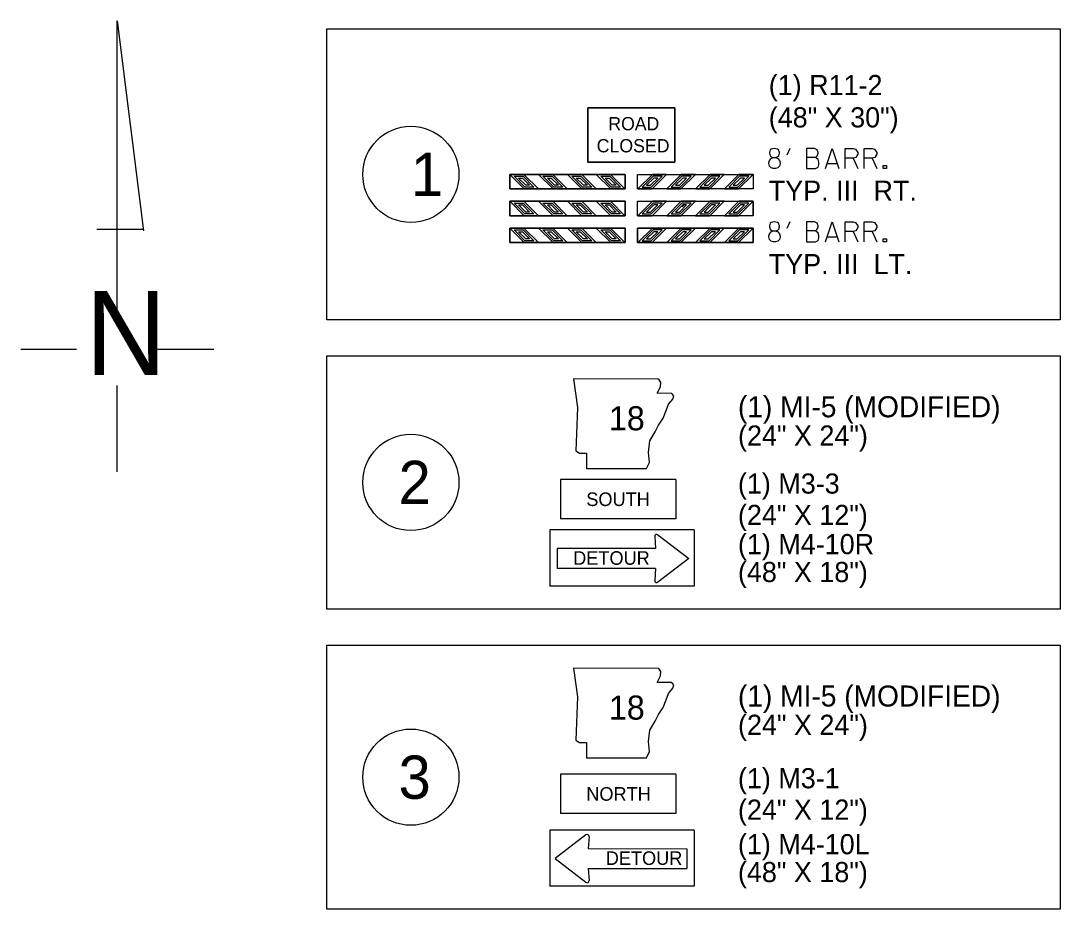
# Model space of a CAD drawing. Extents: x -31818 to 1228740, y -23925 to 152440.
# Drawn here: x -31817.88 to -31789.07, y -23847.72 to -23823.11 of the extents above; entities that cross this region are included whole.
import ezdxf

# ---------------------------------------------------------------- set-up
doc = ezdxf.new("R2010")
doc.units = 0
for name, color, linetype in [('21', 7, 'Continuous'), ('3', 7, 'Continuous'), ('59', 7, 'Continuous'), ('8', 7, 'Continuous'), ('Level 3', 7, 'Continuous'), ('Level 8', 7, 'Continuous'), ('shading', 7, 'Continuous')]:
    doc.layers.add(name, color=color, linetype=linetype)

msp = doc.modelspace()

# ---------------------------------------------------------------- linework, layer by layer
at = {"layer": '21'}
for points in [[(-31802.563, -23833.03), (-31802.445, -23833.822), (-31802.499, -23835.023), (-31802.394, -23835.089), (-31802.196, -23835.089), (-31802.196, -23835.511), (-31800.534, -23835.513), (-31800.454, -23835.341), (-31800.481, -23835.064), (-31800.441, -23834.747), (-31800.295, -23834.497), (-31800.203, -23834.312), (-31800.07, -23834.115), (-31799.991, -23833.904), (-31799.925, -23833.732), (-31799.806, -23833.587), (-31799.779, -23833.495), (-31799.832, -23833.429), (-31800.242, -23833.428), (-31800.149, -23833.244), (-31800.135, -23833.125), (-31800.19, -23833.034)], [(-31802.563, -23841.045), (-31802.445, -23841.837), (-31802.499, -23843.038), (-31802.394, -23843.104), (-31802.196, -23843.104), (-31802.196, -23843.527), (-31800.534, -23843.528), (-31800.454, -23843.357), (-31800.481, -23843.079), (-31800.441, -23842.763), (-31800.295, -23842.512), (-31800.203, -23842.328), (-31800.07, -23842.13), (-31799.991, -23841.919), (-31799.925, -23841.747), (-31799.806, -23841.602), (-31799.779, -23841.51), (-31799.832, -23841.444), (-31800.242, -23841.444), (-31800.149, -23841.259), (-31800.135, -23841.14), (-31800.19, -23841.049)]]:
    msp.add_lwpolyline(points, close=True, dxfattribs=at)
at = {"layer": '3'}
for centre, start, end in [((-31800.254, -23837.39), 52.3853, 184.5739), ((-31800.254, -23838.618), 175.4261, 307.6112), ((-31802.181, -23845.706), 355.4261, 127.6147), ((-31802.181, -23846.934), 232.3888, 4.5739)]:
    msp.add_arc(centre, 0.055, start, end, dxfattribs=at)
at = {"layer": '59'}
for p, q in [((-31799.719, -23835.82), (-31802.92, -23835.82)), ((-31802.92, -23835.82), (-31802.92, -23836.906)), ((-31799.719, -23835.82), (-31799.719, -23836.906)), ((-31799.719, -23836.906), (-31802.92, -23836.906)), ((-31799.211, -23837.213), (-31803.217, -23837.213)), ((-31803.217, -23837.213), (-31803.217, -23838.771)), ((-31800.309, -23837.395), (-31800.282, -23837.729)), ((-31800.22, -23837.347), (-31799.366, -23838.004)), ((-31799.211, -23837.213), (-31799.211, -23838.77)), ((-31800.282, -23837.729), (-31803.015, -23837.729)), ((-31803.015, -23837.729), (-31803.015, -23838.28)), ((-31799.366, -23838.004), (-31800.22, -23838.662)), ((-31800.282, -23838.279), (-31803.015, -23838.28)), ((-31800.282, -23838.279), (-31800.308, -23838.614)), ((-31799.211, -23838.77), (-31803.217, -23838.771)), ((-31799.719, -23843.985), (-31802.92, -23843.985)), ((-31802.92, -23843.985), (-31802.92, -23845.071)), ((-31799.719, -23843.985), (-31799.719, -23845.071)), ((-31799.719, -23845.071), (-31802.92, -23845.071)), ((-31799.211, -23845.528), (-31803.217, -23845.528)), ((-31803.217, -23845.528), (-31803.217, -23847.086)), ((-31802.214, -23845.662), (-31803.068, -23846.32)), ((-31802.126, -23845.71), (-31802.153, -23846.044)), ((-31799.211, -23845.528), (-31799.211, -23847.086)), ((-31802.153, -23846.044), (-31799.419, -23846.045)), ((-31799.419, -23846.045), (-31799.419, -23846.595)), ((-31803.068, -23846.32), (-31802.214, -23846.977)), ((-31802.153, -23846.595), (-31799.419, -23846.595)), ((-31802.153, -23846.595), (-31802.126, -23846.929)), ((-31799.211, -23847.086), (-31803.217, -23847.086))]:
    msp.add_line(p, q, dxfattribs=at)
at = {"layer": '8'}
for p, q in [((-31815.207, -23823.106), (-31814.479, -23828.925)), ((-31815.207, -23831.241), (-31815.207, -23823.106)), ((-31815.771, -23828.881), (-31814.478, -23828.881)), ((-31817.882, -23832.2), (-31816.339, -23832.2)), ((-31814.18, -23832.2), (-31812.532, -23832.2)), ((-31815.207, -23835.605), (-31815.207, -23833.213))]:
    msp.add_line(p, q, dxfattribs=at)
for points in [[(-31809.402, -23823.333), (-31789.067, -23823.333), (-31789.067, -23831.39), (-31809.402, -23831.39)], [(-31809.402, -23832.39), (-31789.067, -23832.39), (-31789.067, -23839.405), (-31809.402, -23839.405)], [(-31809.402, -23840.405), (-31789.067, -23840.405), (-31789.067, -23847.722), (-31809.402, -23847.722)]]:
    msp.add_lwpolyline(points, close=True, dxfattribs=at)
at = {"layer": 'Level 3'}
for p, q in [((-31804.325, -23827.763), (-31804.327, -23827.76)), ((-31797.583, -23827.763), (-31797.581, -23827.76)), ((-31804.327, -23828.508), (-31804.327, -23828.107)), ((-31797.581, -23828.508), (-31797.581, -23828.107))]:
    msp.add_line(p, q, dxfattribs=at)
for points in [[(-31804.327, -23827.362), (-31803.933, -23827.363), (-31803.534, -23827.763), (-31803.926, -23827.763)], [(-31803.527, -23827.362), (-31803.133, -23827.363), (-31802.734, -23827.763), (-31803.126, -23827.763)], [(-31802.727, -23827.362), (-31802.333, -23827.363), (-31801.934, -23827.763), (-31802.326, -23827.763)], [(-31801.927, -23827.362), (-31801.533, -23827.363), (-31801.134, -23827.763), (-31801.526, -23827.763)], [(-31799.981, -23827.362), (-31800.374, -23827.363), (-31800.774, -23827.763), (-31800.381, -23827.763)], [(-31799.181, -23827.362), (-31799.574, -23827.363), (-31799.974, -23827.763), (-31799.582, -23827.763)], [(-31798.381, -23827.362), (-31798.774, -23827.363), (-31799.174, -23827.763), (-31798.782, -23827.763)], [(-31797.581, -23827.362), (-31797.974, -23827.363), (-31798.374, -23827.763), (-31797.982, -23827.763)], [(-31804.206, -23827.412), (-31803.954, -23827.413), (-31803.655, -23827.713), (-31803.905, -23827.713)], [(-31804.085, -23827.463), (-31803.975, -23827.463), (-31803.775, -23827.663), (-31803.885, -23827.663)], [(-31803.406, -23827.412), (-31803.154, -23827.413), (-31802.855, -23827.713), (-31803.106, -23827.713)], [(-31803.285, -23827.463), (-31803.175, -23827.463), (-31802.975, -23827.663), (-31803.085, -23827.663)], [(-31802.606, -23827.412), (-31802.354, -23827.413), (-31802.055, -23827.713), (-31802.306, -23827.713)], [(-31802.485, -23827.463), (-31802.375, -23827.463), (-31802.175, -23827.663), (-31802.285, -23827.663)], [(-31801.806, -23827.412), (-31801.554, -23827.413), (-31801.255, -23827.713), (-31801.506, -23827.713)], [(-31801.685, -23827.463), (-31801.575, -23827.463), (-31801.375, -23827.663), (-31801.485, -23827.663)], [(-31800.102, -23827.412), (-31800.354, -23827.413), (-31800.653, -23827.713), (-31800.402, -23827.713)], [(-31800.223, -23827.463), (-31800.333, -23827.463), (-31800.532, -23827.663), (-31800.423, -23827.663)], [(-31799.302, -23827.412), (-31799.554, -23827.413), (-31799.853, -23827.713), (-31799.602, -23827.713)], [(-31799.423, -23827.463), (-31799.533, -23827.463), (-31799.732, -23827.663), (-31799.623, -23827.663)], [(-31798.502, -23827.412), (-31798.754, -23827.413), (-31799.053, -23827.713), (-31798.802, -23827.713)], [(-31798.623, -23827.463), (-31798.733, -23827.463), (-31798.933, -23827.663), (-31798.823, -23827.663)], [(-31797.702, -23827.412), (-31797.954, -23827.413), (-31798.253, -23827.713), (-31798.002, -23827.713)], [(-31797.823, -23827.463), (-31797.933, -23827.463), (-31798.133, -23827.663), (-31798.023, -23827.663)], [(-31804.327, -23828.107), (-31803.933, -23828.108), (-31803.534, -23828.508), (-31803.926, -23828.508)], [(-31804.206, -23828.158), (-31803.954, -23828.158), (-31803.655, -23828.458), (-31803.905, -23828.458)], [(-31804.085, -23828.208), (-31803.975, -23828.208), (-31803.775, -23828.408), (-31803.885, -23828.408)], [(-31803.527, -23828.107), (-31803.133, -23828.108), (-31802.734, -23828.508), (-31803.126, -23828.508)], [(-31803.406, -23828.158), (-31803.154, -23828.158), (-31802.855, -23828.458), (-31803.106, -23828.458)], [(-31803.285, -23828.208), (-31803.175, -23828.208), (-31802.975, -23828.408), (-31803.085, -23828.408)], [(-31802.727, -23828.107), (-31802.333, -23828.108), (-31801.934, -23828.508), (-31802.326, -23828.508)], [(-31802.606, -23828.158), (-31802.354, -23828.158), (-31802.055, -23828.458), (-31802.306, -23828.458)], [(-31802.485, -23828.208), (-31802.375, -23828.208), (-31802.175, -23828.408), (-31802.285, -23828.408)], [(-31801.927, -23828.107), (-31801.533, -23828.108), (-31801.134, -23828.508), (-31801.526, -23828.508)], [(-31801.806, -23828.158), (-31801.554, -23828.158), (-31801.255, -23828.458), (-31801.506, -23828.458)], [(-31801.685, -23828.208), (-31801.575, -23828.208), (-31801.375, -23828.408), (-31801.485, -23828.408)], [(-31799.981, -23828.107), (-31800.374, -23828.108), (-31800.774, -23828.508), (-31800.381, -23828.508)], [(-31800.102, -23828.158), (-31800.354, -23828.158), (-31800.653, -23828.458), (-31800.402, -23828.458)], [(-31800.223, -23828.208), (-31800.333, -23828.208), (-31800.532, -23828.408), (-31800.423, -23828.408)], [(-31799.181, -23828.107), (-31799.574, -23828.108), (-31799.974, -23828.508), (-31799.582, -23828.508)], [(-31799.302, -23828.158), (-31799.554, -23828.158), (-31799.853, -23828.458), (-31799.602, -23828.458)], [(-31799.423, -23828.208), (-31799.533, -23828.208), (-31799.732, -23828.408), (-31799.623, -23828.408)], [(-31799.484, -23828.199), (-31799.544, -23828.258)], [(-31798.381, -23828.107), (-31798.774, -23828.108), (-31799.174, -23828.508), (-31798.782, -23828.508)], [(-31798.502, -23828.158), (-31798.754, -23828.158), (-31799.053, -23828.458), (-31798.802, -23828.458)], [(-31798.623, -23828.208), (-31798.733, -23828.208), (-31798.933, -23828.408), (-31798.823, -23828.408)], [(-31797.581, -23828.107), (-31797.974, -23828.108), (-31798.374, -23828.508), (-31797.982, -23828.508)], [(-31797.702, -23828.158), (-31797.954, -23828.158), (-31798.253, -23828.458), (-31798.002, -23828.458)], [(-31797.823, -23828.208), (-31797.933, -23828.208), (-31798.133, -23828.408), (-31798.023, -23828.408)], [(-31804.327, -23828.85), (-31803.933, -23828.851), (-31803.534, -23829.251), (-31803.926, -23829.251)], [(-31804.206, -23828.9), (-31803.954, -23828.901), (-31803.655, -23829.201), (-31803.905, -23829.201)], [(-31804.085, -23828.951), (-31803.975, -23828.951), (-31803.775, -23829.151), (-31803.885, -23829.151)], [(-31803.527, -23828.85), (-31803.133, -23828.851), (-31802.734, -23829.251), (-31803.126, -23829.251)], [(-31803.406, -23828.9), (-31803.154, -23828.901), (-31802.855, -23829.201), (-31803.106, -23829.201)], [(-31803.285, -23828.951), (-31803.175, -23828.951), (-31802.975, -23829.151), (-31803.085, -23829.151)], [(-31802.727, -23828.85), (-31802.333, -23828.851), (-31801.934, -23829.251), (-31802.326, -23829.251)], [(-31802.606, -23828.9), (-31802.354, -23828.901), (-31802.055, -23829.201), (-31802.306, -23829.201)], [(-31802.485, -23828.951), (-31802.375, -23828.951), (-31802.175, -23829.151), (-31802.285, -23829.151)], [(-31801.927, -23828.85), (-31801.533, -23828.851), (-31801.134, -23829.251), (-31801.526, -23829.251)], [(-31801.806, -23828.9), (-31801.554, -23828.901), (-31801.255, -23829.201), (-31801.506, -23829.201)], [(-31801.685, -23828.951), (-31801.575, -23828.951), (-31801.375, -23829.151), (-31801.485, -23829.151)], [(-31799.981, -23828.85), (-31800.374, -23828.851), (-31800.774, -23829.251), (-31800.381, -23829.251)], [(-31800.102, -23828.9), (-31800.354, -23828.901), (-31800.653, -23829.201), (-31800.402, -23829.201)], [(-31800.223, -23828.951), (-31800.333, -23828.951), (-31800.532, -23829.151), (-31800.423, -23829.151)], [(-31799.181, -23828.85), (-31799.574, -23828.851), (-31799.974, -23829.251), (-31799.582, -23829.251)], [(-31799.302, -23828.9), (-31799.554, -23828.901), (-31799.853, -23829.201), (-31799.602, -23829.201)], [(-31799.423, -23828.951), (-31799.533, -23828.951), (-31799.732, -23829.151), (-31799.623, -23829.151)], [(-31798.381, -23828.85), (-31798.774, -23828.851), (-31799.174, -23829.251), (-31798.782, -23829.251)], [(-31798.502, -23828.9), (-31798.754, -23828.901), (-31799.053, -23829.201), (-31798.802, -23829.201)], [(-31798.623, -23828.951), (-31798.733, -23828.951), (-31798.933, -23829.151), (-31798.823, -23829.151)], [(-31797.581, -23828.85), (-31797.974, -23828.851), (-31798.374, -23829.251), (-31797.982, -23829.251)], [(-31797.702, -23828.9), (-31797.954, -23828.901), (-31798.253, -23829.201), (-31798.002, -23829.201)], [(-31797.823, -23828.951), (-31797.933, -23828.951), (-31798.133, -23829.151), (-31798.023, -23829.151)]]:
    msp.add_lwpolyline(points, close=True, dxfattribs=at)
at = {"layer": 'Level 8'}
for p, q in [((-31796.558, -23826.641), (-31796.646, -23826.826)), ((-31795.252, -23827.068), (-31795.529, -23827.068)), ((-31794.808, -23826.914), (-31794.681, -23827.199)), ((-31794.281, -23826.914), (-31794.153, -23827.199)), ((-31796.558, -23828.674), (-31796.646, -23828.859)), ((-31794.808, -23828.947), (-31794.681, -23829.233)), ((-31794.281, -23828.947), (-31794.153, -23829.233)), ((-31795.252, -23829.101), (-31795.529, -23829.101))]:
    msp.add_line(p, q, dxfattribs=at)
for points in [[(-31802.161, -23825.516), (-31799.747, -23825.516), (-31799.747, -23827.024), (-31802.161, -23827.024)], [(-31804.327, -23827.362), (-31801.125, -23827.362), (-31801.125, -23827.764), (-31804.327, -23827.764)], [(-31800.782, -23827.362), (-31797.581, -23827.362), (-31797.581, -23827.764), (-31800.782, -23827.764)], [(-31804.327, -23828.107), (-31801.125, -23828.107), (-31801.125, -23828.509), (-31804.327, -23828.509)], [(-31800.782, -23828.107), (-31797.581, -23828.107), (-31797.581, -23828.509), (-31800.782, -23828.509)], [(-31804.327, -23828.85), (-31801.125, -23828.85), (-31801.125, -23829.252), (-31804.327, -23829.252)], [(-31800.782, -23828.85), (-31797.581, -23828.85), (-31797.581, -23829.252), (-31800.782, -23829.252)]]:
    msp.add_lwpolyline(points, close=True, dxfattribs=at)
for points in [[(-31796.963, -23826.892), (-31796.897, -23826.87), (-31796.87, -23826.843), (-31796.853, -23826.777), (-31796.853, -23826.751), (-31796.875, -23826.681), (-31796.901, -23826.663), (-31796.989, -23826.641), (-31797.081, -23826.663), (-31797.108, -23826.681), (-31797.13, -23826.751), (-31797.13, -23826.777), (-31797.112, -23826.843), (-31797.086, -23826.87), (-31797.02, -23826.892), (-31796.963, -23826.892), (-31796.897, -23826.922), (-31796.853, -23826.975), (-31796.831, -23827.037), (-31796.831, -23827.059), (-31796.848, -23827.133), (-31796.897, -23827.182), (-31796.958, -23827.199), (-31797.02, -23827.199), (-31797.081, -23827.182), (-31797.13, -23827.133), (-31797.147, -23827.063), (-31797.147, -23827.037), (-31797.125, -23826.975), (-31797.081, -23826.922), (-31797.02, -23826.892)], [(-31795.85, -23826.896), (-31795.802, -23826.843), (-31795.78, -23826.777), (-31795.78, -23826.755), (-31795.802, -23826.681), (-31795.877, -23826.641), (-31796.101, -23826.641), (-31796.101, -23827.199), (-31795.85, -23827.199), (-31795.78, -23827.16), (-31795.754, -23827.085), (-31795.754, -23827.019), (-31795.78, -23826.953), (-31795.85, -23826.896), (-31796.101, -23826.896)], [(-31795.573, -23827.199), (-31795.389, -23826.641), (-31795.208, -23827.199)], [(-31795.028, -23827.199), (-31795.028, -23826.641), (-31794.804, -23826.641), (-31794.738, -23826.663), (-31794.681, -23826.751), (-31794.681, -23826.804), (-31794.734, -23826.892), (-31794.804, -23826.914), (-31795.028, -23826.914)], [(-31794.501, -23827.199), (-31794.501, -23826.641), (-31794.276, -23826.641), (-31794.211, -23826.663), (-31794.153, -23826.751), (-31794.153, -23826.804), (-31794.206, -23826.892), (-31794.276, -23826.914), (-31794.501, -23826.914)], [(-31793.973, -23827.112), (-31793.885, -23827.112), (-31793.885, -23827.199), (-31793.973, -23827.199), (-31793.973, -23827.112)], [(-31796.963, -23828.925), (-31796.897, -23828.903), (-31796.87, -23828.877), (-31796.853, -23828.811), (-31796.853, -23828.784), (-31796.875, -23828.714), (-31796.901, -23828.696), (-31796.989, -23828.674), (-31797.081, -23828.696), (-31797.108, -23828.714), (-31797.13, -23828.784), (-31797.13, -23828.811), (-31797.112, -23828.877), (-31797.086, -23828.903), (-31797.02, -23828.925), (-31796.963, -23828.925), (-31796.897, -23828.956), (-31796.853, -23829.008), (-31796.831, -23829.07), (-31796.831, -23829.092), (-31796.848, -23829.167), (-31796.897, -23829.215), (-31796.958, -23829.233), (-31797.02, -23829.233), (-31797.081, -23829.215), (-31797.13, -23829.167), (-31797.147, -23829.096), (-31797.147, -23829.07), (-31797.125, -23829.008), (-31797.081, -23828.956), (-31797.02, -23828.925)], [(-31795.85, -23828.929), (-31795.802, -23828.877), (-31795.78, -23828.811), (-31795.78, -23828.789), (-31795.802, -23828.714), (-31795.877, -23828.674), (-31796.101, -23828.674), (-31796.101, -23829.233), (-31795.85, -23829.233), (-31795.78, -23829.193), (-31795.754, -23829.118), (-31795.754, -23829.052), (-31795.78, -23828.986), (-31795.85, -23828.929), (-31796.101, -23828.929)], [(-31795.573, -23829.233), (-31795.389, -23828.674), (-31795.208, -23829.233)], [(-31795.028, -23829.233), (-31795.028, -23828.674), (-31794.804, -23828.674), (-31794.738, -23828.696), (-31794.681, -23828.784), (-31794.681, -23828.837), (-31794.734, -23828.925), (-31794.804, -23828.947), (-31795.028, -23828.947)], [(-31794.501, -23829.233), (-31794.501, -23828.674), (-31794.276, -23828.674), (-31794.211, -23828.696), (-31794.153, -23828.784), (-31794.153, -23828.837), (-31794.206, -23828.925), (-31794.276, -23828.947), (-31794.501, -23828.947)], [(-31793.973, -23829.145), (-31793.885, -23829.145), (-31793.885, -23829.233), (-31793.973, -23829.233), (-31793.973, -23829.145)]]:
    msp.add_lwpolyline(points, dxfattribs=at)
for centre in [(-31807.068, -23827.361), (-31807.068, -23835.897), (-31807.068, -23844.064)]:
    msp.add_circle(centre, 1.333, dxfattribs=at)
at = {"layer": 'shading'}
for p, q in [((-31799.747, -23825.516), (-31802.161, -23825.516)), ((-31802.161, -23825.516), (-31802.161, -23827.024)), ((-31799.747, -23827.024), (-31799.747, -23825.516)), ((-31802.161, -23827.024), (-31799.747, -23827.024)), ((-31801.125, -23827.362), (-31804.327, -23827.362)), ((-31804.327, -23827.362), (-31804.327, -23827.764)), ((-31801.125, -23827.764), (-31801.125, -23827.362)), ((-31800.782, -23827.764), (-31800.782, -23827.362)), ((-31800.782, -23827.362), (-31797.581, -23827.362)), ((-31797.581, -23827.362), (-31797.581, -23827.764)), ((-31804.327, -23827.764), (-31801.125, -23827.764)), ((-31797.581, -23827.764), (-31800.782, -23827.764)), ((-31801.125, -23828.107), (-31804.327, -23828.107)), ((-31804.327, -23828.107), (-31804.327, -23828.508)), ((-31801.125, -23828.508), (-31801.125, -23828.107)), ((-31800.782, -23828.508), (-31800.782, -23828.107)), ((-31800.782, -23828.107), (-31797.581, -23828.107)), ((-31797.581, -23828.107), (-31797.581, -23828.508)), ((-31804.327, -23828.508), (-31801.125, -23828.508)), ((-31797.581, -23828.508), (-31800.782, -23828.508)), ((-31801.125, -23828.85), (-31804.327, -23828.85)), ((-31804.327, -23828.85), (-31804.327, -23829.251)), ((-31801.125, -23829.251), (-31801.125, -23828.85)), ((-31797.581, -23828.85), (-31800.782, -23828.85)), ((-31800.782, -23828.85), (-31800.782, -23829.251)), ((-31797.581, -23829.251), (-31797.581, -23828.85)), ((-31804.327, -23829.251), (-31801.125, -23829.251)), ((-31800.782, -23829.251), (-31797.581, -23829.251))]:
    msp.add_line(p, q, dxfattribs=at)
for centre in [(-31807.068, -23827.361), (-31807.068, -23835.897), (-31807.068, -23844.064)]:
    msp.add_circle(centre, 1.333, dxfattribs=at)

# ---------------------------------------------------------------- texts
at = {"layer": '3'}
for s, p in [('SOUTH', (-31802.205, -23836.551)), ('DETOUR', (-31802.568, -23838.179)), ('NORTH', (-31802.205, -23844.716)), ('DETOUR', (-31801.665, -23846.495))]:
    msp.add_text(s, height=0.3759, rotation=360, dxfattribs=at).set_placement(p)
at = {"layer": '8'}
for s, height, p in [('N', 2.327, (-31816.089, -23832.917)), ('18', 0.667, (-31801.577, -23834.453)), ('18', 0.667, (-31801.577, -23842.469))]:
    msp.add_text(s, height=height, dxfattribs=at).set_placement(p)
at = {"layer": 'Level 3'}
for s, height, p in [('ROAD', 0.3654, (-31801.593, -23826.139)), ('CLOSED', 0.3672, (-31801.917, -23826.751))]:
    msp.add_text(s, height=height, dxfattribs=at).set_placement(p)
at = {"layer": 'Level 8'}
for s, height, p in [('(1) R11-2', 0.5583, (-31797.147, -23825.166)), ('(48" X 30")', 0.55832, (-31797.147, -23826.06)), ('1', 1.2, (-31807.068, -23827.961)), ('TYP. III  RT.', 0.55832, (-31797.147, -23828.093)), ('TYP. III  LT.', 0.55832, (-31797.147, -23830.126)), ('2', 1.2, (-31807.409, -23836.497)), ('3', 1.2, (-31807.409, -23844.664))]:
    msp.add_text(s, height=height, dxfattribs=at).set_placement(p)
for s, height, rotation, p in [('(1) MI-5 (MODIFIED)', 0.58333, 360, (-31798.001, -23834.092)), ('(24" X 24")', 0.55832, 0, (-31797.999, -23834.877)), ('(1) M3-3', 0.5583, 0, (-31798.001, -23836.207)), ('(24" X 12")', 0.55832, 0, (-31798.001, -23837.077)), ('(1) M4-10R', 0.5583, 0, (-31798.001, -23837.885)), ('(48" X 18")', 0.55832, 0, (-31798.001, -23838.657)), ('(1) MI-5 (MODIFIED)', 0.58333, 360, (-31798.001, -23842.107)), ('(24" X 24")', 0.55832, 0, (-31797.999, -23842.892)), ('(1) M3-1', 0.5583, 0, (-31798.001, -23844.372)), ('(24" X 12")', 0.55832, 0, (-31798.001, -23845.242)), ('(1) M4-10L', 0.5583, 0, (-31798.001, -23846.2)), ('(48" X 18")', 0.55832, 0, (-31798.001, -23846.972))]:
    msp.add_text(s, height=height, rotation=rotation, dxfattribs=at).set_placement(p)

doc.saveas('drawing.dxf')
